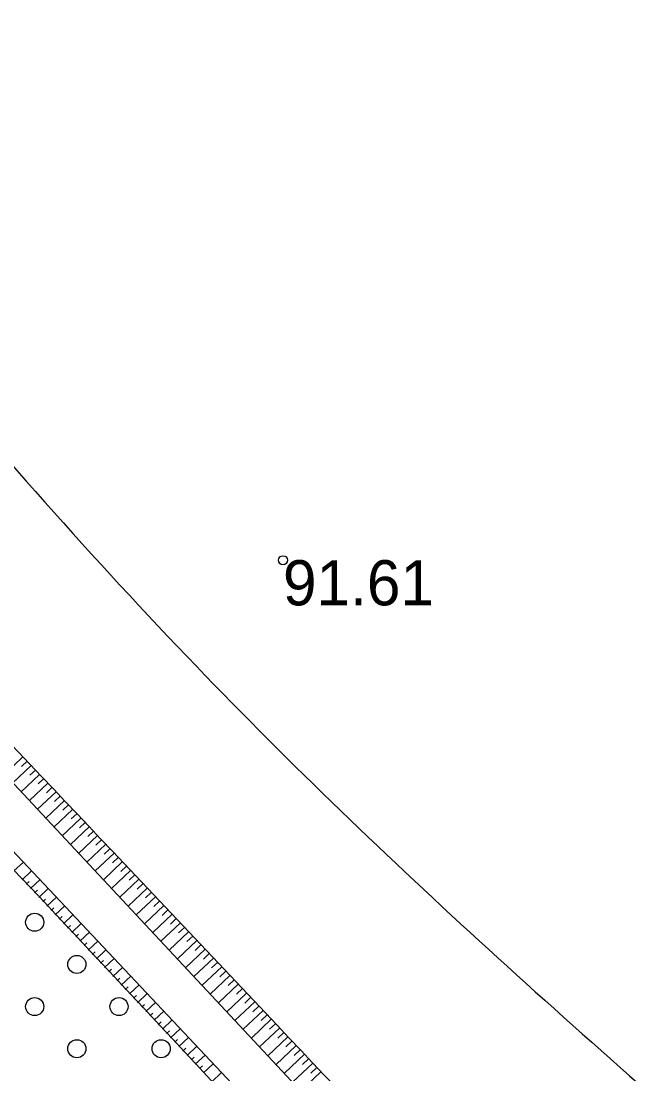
# Model space of a CAD drawing. Extents: x 316000 to 728450, y 314368 to 726000.
# Drawn here: x 725968.9 to 726019.5, y 315372.4 to 315459.8 of the extents above; entities that cross this region are included whole.
import ezdxf

# ---------------------------------------------------------------- set-up
doc = ezdxf.new("R2010")
doc.units = 0
for name, color, linetype in [('HIDG_GRAV_####_####_#', 7, 'Continuous'), ('RELJ_AATZ_####_TKST_#', 7, 'Continuous'), ('RELJ_ELEM_####_####_#', 7, 'Continuous'), ('RELJ_HORZ_PAMT_####_#', 7, 'Continuous'), ('RELJ_NOGA_####_####_#', 7, 'Continuous'), ('TERT_ELEM_####_####_#', 7, 'Continuous')]:
    doc.layers.add(name, color=color, linetype=linetype)

msp = doc.modelspace()

# ---------------------------------------------------------------- linework, layer by layer
at = {"layer": 'HIDG_GRAV_####_####_#'}
for points in [[(726259.175, 315086.515), (726260.768, 315088.859), (726179.005, 315175.766), (726127.859, 315229.056), (726063.055, 315296.073), (725998.338, 315364.317), (725936.648, 315430.32), (725875.345, 315494.083), (725809.436, 315562.192), (725743.944, 315631.872)], [(725741.161, 315628.109), (725806.062, 315558.993), (725870.895, 315491.871), (725934.12, 315427.077), (725995.775, 315361.632), (726059.846, 315293.396), (726126.03, 315226.728), (726194.491, 315154.86), (726259.175, 315086.515)]]:
    msp.add_lwpolyline(points, dxfattribs=at)
at = {"layer": 'RELJ_ELEM_####_####_#'}
msp.add_circle((725990.612, 315415.057), 0.375, dxfattribs=at)
at = {"layer": 'RELJ_HORZ_PAMT_####_#'}
msp.add_spline([(726116.344, 315699.088), (726105.94, 315702.687), (726040.128, 315715), (725990.823, 315710.424), (725942.032, 315708.248), (725920.28, 315706.773), (725880.366, 315714.514), (725859.054, 315708.681), (725859.054, 315672.662), (725851.263, 315613.969), (725853.471, 315568.895), (725840.997, 315555.788), (725885.558, 315509.629), (725935.943, 315461.491), (725983.423, 315406.25), (726032.861, 315360.511), (726082.852, 315311.191), (726122.235, 315248.757), (726137.049, 315229.286), (726180.187, 315183.1), (726194.517, 315168.27), (726211.91, 315146.926), (726212.513, 315143.157)], degree=3, dxfattribs=at)
at = {"layer": 'RELJ_NOGA_####_####_#'}
for p, q in [((725969.021, 315398.726), (725967.514, 315397.296)), ((725969.709, 315398.001), (725968.197, 315396.565)), ((725969.365, 315398.363), (725968.912, 315397.934)), ((725970.398, 315397.275), (725968.879, 315395.835)), ((725970.054, 315397.638), (725969.599, 315397.207)), ((725970.742, 315396.912), (725970.285, 315396.48)), ((725971.086, 315396.549), (725969.562, 315395.105)), ((725971.43, 315396.187), (725970.972, 315395.752)), ((725971.774, 315395.824), (725970.245, 315394.374)), ((725972.118, 315395.461), (725971.658, 315395.025)), ((725972.462, 315395.098), (725970.927, 315393.644)), ((725973.15, 315394.372), (725971.61, 315392.913)), ((725972.806, 315394.735), (725972.345, 315394.298)), ((725973.838, 315393.647), (725972.293, 315392.183)), ((725973.494, 315394.009), (725973.031, 315393.571)), ((725974.526, 315392.921), (725972.976, 315391.452)), ((725974.182, 315393.284), (725973.718, 315392.844)), ((725974.869, 315392.558), (725974.404, 315392.117)), ((725975.213, 315392.195), (725973.658, 315390.722)), ((725975.557, 315391.832), (725975.09, 315391.389)), ((725975.901, 315391.469), (725974.341, 315389.991)), ((725976.589, 315390.743), (725975.024, 315389.261)), ((725976.245, 315391.106), (725975.776, 315390.662)), ((725968.278, 315389.254), (725969.061, 315389.988)), ((725977.276, 315390.017), (725975.707, 315388.531)), ((725976.933, 315390.38), (725976.463, 315389.935)), ((725968.963, 315388.525), (725969.746, 315389.261)), ((725977.964, 315389.291), (725976.39, 315387.8)), ((725977.62, 315389.654), (725977.149, 315389.207)), ((725969.305, 315388.16), (725969.54, 315388.381)), ((725969.648, 315387.796), (725970.432, 315388.533)), ((725978.652, 315388.565), (725977.072, 315387.069)), ((725978.308, 315388.928), (725977.835, 315388.48)), ((725978.995, 315388.202), (725978.521, 315387.752)), ((725969.99, 315387.431), (725970.225, 315387.653)), ((725970.332, 315387.067), (725971.118, 315387.805)), ((725979.339, 315387.838), (725977.755, 315386.339)), ((725979.683, 315387.475), (725979.207, 315387.025)), ((725970.674, 315386.702), (725970.91, 315386.924)), ((725971.017, 315386.338), (725971.804, 315387.077)), ((725980.027, 315387.112), (725978.438, 315385.609)), ((725980.714, 315386.386), (725979.121, 315384.878)), ((725980.37, 315386.749), (725979.893, 315386.297)), ((725971.359, 315385.973), (725971.595, 315386.195)), ((725971.701, 315385.609), (725972.489, 315386.349)), ((725972.385, 315384.88), (725973.175, 315385.621)), ((725981.401, 315385.66), (725979.803, 315384.147)), ((725981.058, 315386.023), (725980.579, 315385.57)), ((725972.043, 315385.244), (725972.28, 315385.466)), ((725972.728, 315384.515), (725972.965, 315384.738)), ((725973.07, 315384.151), (725973.861, 315384.893)), ((725982.089, 315384.933), (725980.486, 315383.417)), ((725981.745, 315385.296), (725981.265, 315384.842)), ((725973.412, 315383.786), (725973.65, 315384.009)), ((725973.754, 315383.421), (725974.547, 315384.165)), ((725982.776, 315384.207), (725981.169, 315382.687)), ((725982.432, 315384.57), (725981.951, 315384.115)), ((725983.12, 315383.844), (725982.637, 315383.387)), ((725974.097, 315383.057), (725974.334, 315383.28)), ((725974.439, 315382.692), (725975.232, 315383.437)), ((725983.463, 315383.481), (725981.852, 315381.956)), ((725983.807, 315383.117), (725983.323, 315382.659)), ((725974.781, 315382.328), (725975.019, 315382.552)), ((725975.123, 315381.963), (725975.918, 315382.71)), ((725984.15, 315382.754), (725982.534, 315381.225)), ((725984.838, 315382.028), (725983.217, 315380.495)), ((725984.494, 315382.391), (725984.009, 315381.932)), ((725975.465, 315381.599), (725975.704, 315381.823)), ((725975.808, 315381.234), (725976.604, 315381.982)), ((725976.492, 315380.505), (725977.289, 315381.254)), ((725985.525, 315381.301), (725983.9, 315379.764)), ((725985.181, 315381.664), (725984.694, 315381.204)), ((725976.15, 315380.87), (725976.389, 315381.094)), ((725976.834, 315380.141), (725977.074, 315380.365)), ((725977.176, 315379.776), (725977.975, 315380.526)), ((725986.212, 315380.574), (725984.583, 315379.034)), ((725985.868, 315380.938), (725985.38, 315380.476)), ((725977.519, 315379.412), (725977.759, 315379.637)), ((725977.861, 315379.047), (725978.661, 315379.798)), ((725986.899, 315379.848), (725985.265, 315378.303)), ((725986.555, 315380.211), (725986.066, 315379.748)), ((725987.242, 315379.485), (725986.752, 315379.021)), ((725978.203, 315378.683), (725978.443, 315378.908)), ((725978.545, 315378.318), (725979.347, 315379.07)), ((725987.586, 315379.121), (725985.948, 315377.573)), ((725987.929, 315378.758), (725987.438, 315378.293)), ((725978.888, 315377.953), (725979.128, 315378.179)), ((725979.23, 315377.589), (725980.032, 315378.342)), ((725988.273, 315378.395), (725986.631, 315376.842)), ((725988.96, 315377.668), (725987.314, 315376.112)), ((725988.616, 315378.031), (725988.123, 315377.565)), ((725979.572, 315377.224), (725979.813, 315377.451)), ((725979.914, 315376.86), (725980.718, 315377.614)), ((725980.599, 315376.131), (725981.404, 315376.887)), ((725989.647, 315376.941), (725987.997, 315375.381)), ((725989.303, 315377.305), (725988.809, 315376.837)), ((725980.256, 315376.495), (725980.498, 315376.722)), ((725980.941, 315375.766), (725981.183, 315375.993)), ((725981.283, 315375.402), (725982.09, 315376.159)), ((725990.334, 315376.214), (725988.679, 315374.651)), ((725989.99, 315376.578), (725989.495, 315376.109)), ((725981.625, 315375.037), (725981.867, 315375.264)), ((725981.968, 315374.673), (725982.775, 315375.431)), ((725991.021, 315375.488), (725989.362, 315373.92)), ((725990.677, 315375.851), (725990.18, 315375.381)), ((725991.364, 315375.124), (725990.866, 315374.653)), ((725982.31, 315374.308), (725982.552, 315374.536)), ((725982.652, 315373.944), (725983.461, 315374.703)), ((725991.707, 315374.761), (725990.045, 315373.19)), ((725992.051, 315374.398), (725991.552, 315373.926)), ((725982.994, 315373.579), (725983.237, 315373.807)), ((725983.337, 315373.215), (725984.146, 315373.975)), ((725992.394, 315374.034), (725990.728, 315372.459)), ((725993.081, 315373.307), (725991.41, 315371.729)), ((725992.738, 315373.671), (725992.237, 315373.198)), ((725983.679, 315372.85), (725983.922, 315373.079)), ((725984.021, 315372.486), (725984.832, 315373.247)), ((725984.706, 315371.757), (725985.518, 315372.52)), ((725993.768, 315372.58), (725992.093, 315370.998)), ((725993.424, 315372.944), (725992.923, 315372.47))]:
    msp.add_line(p, q, dxfattribs=at)
for points in [[(726259.118, 315084.507), (726262.723, 315089.259), (726261.561, 315090.837), (726260.205, 315092.42), (726257.293, 315095.532), (726218.912, 315136.383), (726180.307, 315176.838), (726128.672, 315229.97), (726063.701, 315298.11), (725999.895, 315366.094), (725937.206, 315432.091), (725876.347, 315495.232), (725810.578, 315563.083), (725744.701, 315632.911)], [(725740.862, 315626.984), (725805.544, 315558.116), (725870.385, 315491.147), (725932.803, 315426.796), (725994.977, 315360.836), (726059.661, 315292.118), (726075.746, 315275.458), (726092.085, 315259.043), (726108.47, 315242.673), (726124.693, 315226.144), (726193.269, 315154.025), (726250.062, 315092.6), (726256.318, 315085.83), (726258.824, 315084.289), (726259.118, 315084.507)]]:
    msp.add_spline(points, degree=3, dxfattribs=at)
at = {"layer": 'TERT_ELEM_####_####_#'}
for centre in [(725970, 315385), (725973.5, 315381.5), (725970, 315378), (725977, 315378), (725973.5, 315374.5), (725980.5, 315374.5)]:
    msp.add_circle(centre, 0.75, dxfattribs=at)

# ---------------------------------------------------------------- texts
at = {"layer": 'RELJ_AATZ_####_TKST_#'}
msp.add_text('91.61', height=3.75, dxfattribs=at).set_placement((725990.612, 315411.307))

doc.saveas('drawing.dxf')
